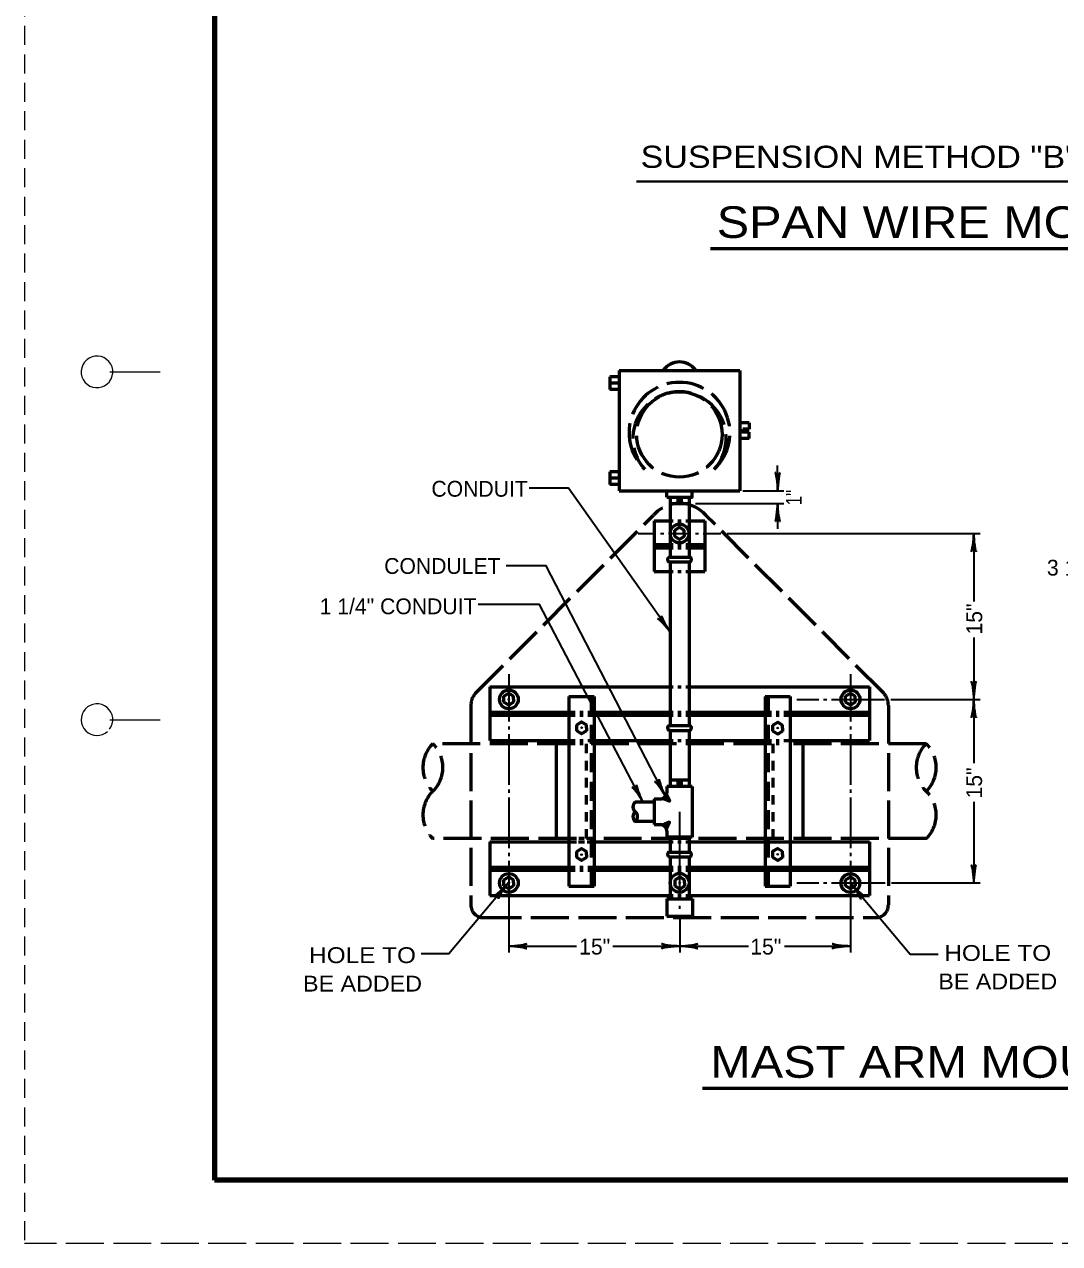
# Model space of a CAD drawing. Extents: x -1 to 679, y 1 to 441.
# Drawn here: x -1.2 to 162.4, y 0.8 to 193.5 of the extents above; entities that cross this region are included whole.
import ezdxf
from ezdxf.enums import TextEntityAlignment as Align

# ---------------------------------------------------------------- set-up
doc = ezdxf.new("R2010")
doc.units = 0
for name, pattern in [('LONG_DASHED', [7.5, 6, -1.5]), ('MEDIUM_DASHED', [4.5, 3, -1.5]), ('SHORT_DASHED', [2.7, 1.5, -1.2])]:
    doc.linetypes.add(name, pattern=pattern)
doc.layers.add('1', color=7, linetype='Continuous', lineweight=35)
doc.layers.add('61', color=7, linetype='Continuous', lineweight=35)

msp = doc.modelspace()

# ---------------------------------------------------------------- hatches: boundary and pattern name
at = {"layer": '1'}
for points in [[(75.433, 86.822, 1), (75.183, 86.822, 1)], [(129.442, 86.794, 1), (129.192, 86.794, 1)], [(86.96, 82.329, 1), (86.71, 82.329, 1)], [(117.958, 82.283, 1), (117.708, 82.283, 1)], [(86.956, 62.257, 1), (86.706, 62.257, 1)], [(117.958, 62.317, 1), (117.708, 62.317, 1)], [(75.456, 57.834, 1), (75.206, 57.834, 1)], [(102.471, 57.779, 1), (102.221, 57.779, 1)], [(129.454, 57.788, 1), (129.204, 57.788, 1)]]:
    msp.add_hatch(color=256, dxfattribs=at).paths.add_polyline_path(points)

# ---------------------------------------------------------------- linework, layer by layer
at = {"layer": '1', "linetype": 'MEDIUM_DASHED', "lineweight": 13}
msp.add_line((-1.178, 440.796), (-1.238, 0.756), dxfattribs=at)
at = {"layer": '1', "lineweight": 40}
msp.add_line((95.529, 168.697), (237.44, 168.697), dxfattribs=at)
at = {"layer": '1', "lineweight": 53}
for p, q in [((107.221, 158.112), (227.893, 158.112)), ((92.794, 138.806), (92.794, 119.806)), ((92.794, 138.806), (111.829, 138.806)), ((111.829, 138.806), (111.829, 119.806)), ((92.794, 137.806), (91.294, 137.806)), ((91.294, 137.806), (91.294, 135.806)), ((92.794, 136.806), (91.294, 136.806)), ((92.794, 135.806), (91.294, 135.806)), ((113.329, 130.556), (111.829, 130.556)), ((113.329, 129.556), (112.329, 129.556)), ((113.329, 130.556), (113.329, 129.556)), ((113.329, 128.056), (111.829, 128.056)), ((113.329, 128.056), (113.329, 129.056)), ((92.794, 122.806), (91.294, 122.806)), ((91.294, 122.806), (91.294, 120.806)), ((92.794, 121.806), (91.294, 121.806)), ((92.794, 120.806), (91.294, 120.806)), ((92.794, 119.806), (111.829, 119.806)), ((100.294, 118.791), (100.294, 119.791)), ((100.829, 118.791), (100.829, 109.291)), ((100.829, 117.791), (103.829, 117.791)), ((101.829, 118.291), (102.829, 118.291)), ((103.829, 118.791), (103.829, 115.041)), ((102.044, 115.041), (102.579, 115.041)), ((103.829, 115.029), (103.829, 109.291)), ((106.329, 115.041), (106.329, 107.041)), ((101.552, 112.585), (101.552, 113.552)), ((103.073, 113.068), (103.073, 113.552)), ((103.073, 113.068), (103.073, 112.585)), ((98.294, 110.791), (100.829, 110.791)), ((100.829, 110.791), (101.294, 110.791)), ((102.044, 111.291), (102.579, 111.291)), ((102.044, 110.791), (102.579, 110.791)), ((103.329, 111.291), (103.829, 111.291)), ((103.329, 110.791), (103.829, 110.791)), ((103.829, 111.291), (106.329, 111.291)), ((103.829, 110.791), (106.329, 110.791)), ((100.829, 109.291), (103.829, 109.291)), ((100.829, 108.541), (103.829, 108.541)), ((100.829, 108.541), (100.829, 84.291)), ((103.829, 108.541), (103.829, 82.666)), ((98.294, 107.041), (101.294, 107.041)), ((102.044, 107.041), (102.579, 107.041)), ((103.329, 107.041), (106.329, 107.041)), ((72.329, 88.791), (101.294, 88.791)), ((102.044, 88.791), (102.579, 88.791)), ((103.329, 88.791), (132.329, 88.791)), ((132.329, 88.791), (132.329, 80.291)), ((74.568, 86.347), (74.568, 87.314)), ((76.089, 86.831), (76.089, 87.314)), ((76.089, 86.831), (76.089, 86.347)), ((84.829, 87.291), (84.829, 57.291)), ((84.829, 87.291), (88.829, 87.291)), ((88.829, 87.291), (88.829, 57.291)), ((115.829, 87.291), (115.829, 57.291)), ((115.829, 87.291), (119.829, 87.291)), ((119.829, 87.291), (119.829, 57.291)), ((128.568, 86.347), (128.568, 87.314)), ((130.089, 86.831), (130.089, 87.314)), ((130.089, 86.831), (130.089, 86.347)), ((72.329, 84.791), (85.829, 84.791)), ((72.329, 84.291), (85.829, 84.291)), ((86.579, 84.791), (87.079, 84.791)), ((86.579, 84.291), (87.079, 84.291)), ((87.829, 84.791), (101.294, 84.791)), ((87.829, 84.291), (101.294, 84.291)), ((100.829, 84.291), (100.829, 82.666)), ((102.044, 84.791), (102.579, 84.791)), ((102.044, 84.291), (102.579, 84.291)), ((103.329, 84.791), (116.829, 84.791)), ((103.329, 84.291), (116.829, 84.291)), ((117.579, 84.791), (118.079, 84.791)), ((117.579, 84.291), (118.079, 84.291)), ((118.829, 84.791), (132.329, 84.791)), ((118.829, 84.291), (132.329, 84.291)), ((86.077, 81.83), (86.077, 82.797)), ((87.598, 82.313), (87.598, 82.797)), ((87.598, 82.313), (87.598, 81.83)), ((100.829, 82.666), (103.829, 82.666)), ((100.829, 81.916), (103.829, 81.916)), ((100.829, 81.916), (100.829, 80.291)), ((103.829, 81.916), (103.829, 73.041)), ((117.076, 81.783), (117.076, 82.751)), ((118.597, 82.267), (118.597, 82.751)), ((118.597, 82.267), (118.597, 81.783)), ((72.329, 80.291), (85.829, 80.291)), ((82.829, 79.791), (82.829, 64.791)), ((86.579, 80.291), (87.079, 80.291)), ((87.829, 80.291), (101.294, 80.291)), ((100.829, 80.291), (100.829, 73.041)), ((102.044, 80.291), (102.579, 80.291)), ((103.329, 80.291), (116.829, 80.291)), ((117.579, 80.291), (118.079, 80.291)), ((118.829, 80.291), (132.329, 80.291)), ((121.829, 79.791), (121.829, 64.791)), ((103.829, 74.041), (100.829, 74.041)), ((102.829, 73.541), (101.829, 73.541)), ((104.329, 73.041), (100.33, 73.041)), ((100.33, 73.041), (100.33, 72.041)), ((104.329, 73.041), (104.329, 65.041)), ((98.329, 70.564), (95.329, 70.564)), ((98.329, 71.064), (98.329, 67.019)), ((98.329, 71.064), (99.329, 71.064)), ((98.329, 67.519), (95.329, 67.519)), ((98.329, 67.019), (99.329, 67.019)), ((100.333, 66.041), (100.333, 65.041)), ((72.329, 64.291), (86.029, 64.291)), ((86.342, 64.291), (87.319, 64.291)), ((87.695, 64.291), (101.294, 64.291)), ((104.329, 65.041), (100.333, 65.041)), ((100.829, 65.041), (100.829, 64.291)), ((100.829, 64.291), (100.829, 62.666)), ((102.044, 64.291), (102.579, 64.291)), ((103.329, 64.291), (132.329, 64.291)), ((103.829, 65.041), (103.829, 64.291)), ((103.829, 64.291), (103.829, 62.666)), ((132.329, 64.291), (132.329, 55.791)), ((86.069, 61.783), (86.069, 62.75)), ((87.59, 62.267), (87.59, 62.75)), ((87.59, 62.267), (87.59, 61.783)), ((100.829, 62.666), (103.829, 62.666)), ((100.829, 61.916), (103.829, 61.916)), ((100.829, 61.916), (100.829, 60.291)), ((103.829, 61.916), (103.829, 60.291)), ((118.597, 62.301), (118.597, 62.785)), ((118.597, 62.301), (118.597, 61.817)), ((72.329, 60.291), (85.829, 60.291)), ((72.329, 59.791), (85.829, 59.791)), ((86.579, 60.291), (87.079, 60.291)), ((86.579, 59.791), (87.079, 59.791)), ((87.829, 60.291), (101.294, 60.291)), ((87.829, 59.791), (101.294, 59.791)), ((100.829, 60.291), (100.829, 55.291)), ((102.044, 60.291), (102.579, 60.291)), ((102.044, 59.791), (102.579, 59.791)), ((103.329, 60.291), (132.329, 60.291)), ((103.329, 59.791), (132.329, 59.791)), ((103.829, 60.291), (103.829, 55.291)), ((74.569, 57.327), (74.569, 58.294)), ((76.09, 57.81), (76.09, 58.294)), ((101.603, 57.296), (101.603, 58.263)), ((103.124, 57.779), (103.124, 58.263)), ((128.557, 57.303), (128.557, 58.271)), ((130.078, 57.787), (130.078, 58.271)), ((76.09, 57.81), (76.09, 57.327)), ((84.829, 57.291), (88.829, 57.291)), ((103.124, 57.779), (103.124, 57.296)), ((115.829, 57.291), (119.829, 57.291)), ((130.078, 57.787), (130.078, 57.303)), ((72.329, 55.791), (101.294, 55.791)), ((100.333, 55.291), (104.378, 55.291)), ((100.333, 55.291), (100.333, 52.541)), ((102.044, 55.791), (102.579, 55.791)), ((103.329, 55.791), (132.329, 55.791)), ((104.378, 55.291), (104.378, 52.541)), ((100.333, 52.541), (104.378, 52.541)), ((105.933, 25.316), (220.597, 25.316))]:
    msp.add_line(p, q, dxfattribs=at)
at = {"layer": '1'}
for p, q in [((117.829, 119.806), (117.829, 123.806)), ((112.329, 119.806), (118.829, 119.806)), ((104.829, 117.791), (118.829, 117.791)), ((117.829, 117.791), (117.829, 113.791)), ((95.794, 113.041), (98.561, 113.041)), ((99.311, 113.041), (99.811, 113.041)), ((100.561, 113.041), (104.079, 113.041)), ((104.829, 113.041), (105.329, 113.041)), ((106.079, 113.041), (108.829, 113.041)), ((109.829, 113.041), (149.829, 113.041)), ((148.829, 113.041), (148.829, 102.304)), ((75.329, 90.791), (75.329, 83.291)), ((129.329, 90.791), (129.329, 83.291)), ((120.858, 86.791), (124.329, 86.791)), ((125.079, 86.791), (125.579, 86.791)), ((126.329, 86.791), (134.704, 86.791)), ((135.704, 86.791), (149.829, 86.791)), ((75.329, 82.541), (75.329, 82.041)), ((75.329, 81.291), (75.329, 73.291)), ((129.329, 82.541), (129.329, 82.041)), ((129.329, 81.291), (129.329, 73.291)), ((75.329, 72.541), (75.329, 72.041)), ((129.329, 72.541), (129.329, 72.041)), ((75.329, 71.291), (75.329, 63.291)), ((129.329, 71.291), (129.329, 63.291)), ((148.829, 70.63), (148.829, 57.791)), ((102.356, 62.666), (102.356, 69.041)), ((75.329, 62.541), (75.329, 62.041)), ((102.356, 62.166), (102.356, 62.416)), ((102.356, 55.291), (102.356, 61.916)), ((129.329, 62.541), (129.329, 62.041)), ((75.329, 61.291), (75.329, 46.791)), ((129.329, 61.291), (129.329, 46.791)), ((120.858, 57.791), (124.329, 57.791)), ((125.079, 57.791), (125.579, 57.791)), ((126.329, 57.791), (134.829, 57.791)), ((135.829, 57.791), (149.829, 57.791)), ((102.356, 53.666), (102.356, 54.166)), ((102.356, 52.166), (102.356, 46.791)), ((75.329, 47.791), (86.055, 47.791)), ((118.907, 47.791), (129.329, 47.791))]:
    msp.add_line(p, q, dxfattribs=at)
at = {"layer": '1', "linetype": 'LONG_DASHED', "lineweight": 53}
for p, q in [((70.207, 87.943), (98.208, 115.944)), ((134.45, 87.943), (106.449, 115.944)), ((69.329, 85.822), (69.329, 54.297)), ((135.329, 85.822), (135.329, 54.297)), ((85.829, 79.791), (63.329, 79.791)), ((87.079, 79.791), (86.579, 79.791)), ((116.829, 79.791), (87.829, 79.791)), ((118.079, 79.791), (117.579, 79.791)), ((141.329, 79.791), (118.829, 79.791)), ((86.011, 64.791), (63.329, 64.791)), ((87.238, 64.791), (86.387, 64.791)), ((141.329, 64.791), (87.614, 64.791)), ((71.329, 52.297), (133.329, 52.297))]:
    msp.add_line(p, q, dxfattribs=at)
at = {"layer": '1', "linetype": 'MEDIUM_DASHED', "lineweight": 53}
for p, q in [((88.329, 87.291), (88.329, 57.291)), ((116.329, 87.291), (116.329, 57.291))]:
    msp.add_line(p, q, dxfattribs=at)
at = {"layer": '1', "linetype": 'SHORT_DASHED', "lineweight": 53}
for p, q in [((87.579, 79.791), (87.579, 64.791)), ((117.079, 79.791), (117.079, 64.791))]:
    msp.add_line(p, q, dxfattribs=at)
at = {"layer": '1', "lineweight": 53}
for points in [[(113.329, 129.056), (112.329, 129.056), (112.329, 129.556)], [(100.294, 118.791), (104.329, 118.791), (104.329, 119.791)], [(98.294, 115.041), (100.829, 115.041), (101.294, 115.041)], [(98.294, 115.041), (98.294, 110.791), (98.294, 107.041)], [(101.552, 113.552), (102.312, 114.023), (103.073, 113.552)], [(103.329, 115.041), (103.829, 115.041), (106.329, 115.041)], [(103.073, 112.585), (102.312, 112.115), (101.552, 112.585)], [(98.294, 111.291), (100.829, 111.291), (101.294, 111.291)], [(72.329, 88.791), (72.329, 84.791), (72.329, 80.291)], [(74.568, 87.314), (75.329, 87.785), (76.089, 87.314)], [(128.568, 87.314), (129.329, 87.785), (130.089, 87.314)], [(76.089, 86.347), (75.329, 85.878), (74.568, 86.347)], [(130.089, 86.347), (129.329, 85.878), (128.568, 86.347)], [(86.077, 82.797), (86.838, 83.268), (87.598, 82.797)], [(117.076, 82.751), (117.837, 83.222), (118.597, 82.751)], [(87.598, 81.83), (86.838, 81.36), (86.077, 81.83)], [(118.597, 81.783), (117.837, 81.314), (117.076, 81.783)], [(100.251, 71.738), (100.736, 70.692), (99.645, 71.139)], [(100.255, 66.344), (100.74, 67.39), (99.649, 66.943)], [(72.329, 64.291), (72.329, 60.291), (72.329, 59.791), (72.329, 55.791)], [(86.069, 62.75), (86.829, 63.221), (87.59, 62.75)], [(87.59, 61.783), (86.829, 61.314), (86.069, 61.783)], [(117.076, 61.817), (117.076, 62.785), (117.837, 63.256), (118.597, 62.785)], [(118.597, 61.817), (117.837, 61.348), (117.076, 61.817)], [(74.569, 58.294), (75.33, 58.765), (76.09, 58.294)], [(101.603, 58.263), (102.364, 58.734), (103.124, 58.263)], [(128.557, 58.271), (129.317, 58.742), (130.078, 58.271)], [(76.09, 57.327), (75.33, 56.857), (74.569, 57.327)], [(103.124, 57.296), (102.364, 56.826), (101.603, 57.296)], [(130.078, 57.303), (129.317, 56.834), (128.557, 57.303)]]:
    msp.add_lwpolyline(points, dxfattribs=at)
at = {"layer": '1'}
for points in [[(100.829, 97.467), (84.77, 120.225), (78.531, 120.225)], [(100.077, 71.452), (81.249, 107.916), (74.936, 107.916)], [(96.515, 70.564), (80.185, 101.815), (70.468, 101.815)], [(148.829, 96.591), (148.829, 86.791), (148.829, 76.705)], [(75.228, 57.751), (65.856, 46.593), (61.474, 46.593)], [(129.422, 57.669), (138.793, 46.511), (143.175, 46.511)], [(91.751, 47.791), (102.356, 47.791), (113.21, 47.791)]]:
    msp.add_lwpolyline(points, dxfattribs=at)
at = {"layer": '1', "linetype": 'LONG_DASHED', "lineweight": 53}
msp.add_circle((102.301, 128.701), 6.75, dxfattribs=at)
at = {"layer": '1', "lineweight": 53}
for centre in [(102.325, 113.043), (75.341, 86.805), (129.341, 86.805), (75.342, 57.785), (102.334, 57.802), (129.33, 57.761)]:
    msp.add_circle(centre, 1.483, dxfattribs=at)
at = {"layer": '1', "lineweight": 13}
for centre in [(75.308, 86.822), (129.317, 86.794), (86.835, 82.329), (117.833, 82.283), (86.831, 62.257), (117.833, 62.317), (75.331, 57.834), (102.346, 57.779), (129.329, 57.788)]:
    msp.add_circle(centre, 0.125, dxfattribs=at)
at = {"layer": '1', "lineweight": 53}
for centre, radius, start, end in [((102.311, 137), 3.159, 37.18292, 142.81708), ((100.797, 108.917), 0.376, 85.2092, 274.79081), ((103.86, 108.917), 0.376, 265.20919, 94.7908), ((100.797, 82.292), 0.376, 85.2092, 274.79081), ((103.86, 82.292), 0.376, 265.20919, 94.7908), ((99.233, 72.163), 1.103, 291.91656, 353.67636), ((99.233, 72.163), 1.103, 291.91738, 337.37313), ((95.903, 69.803), 0.954, 127.04437, 232.95563), ((99.233, 72.163), 1.103, 274.9623, 291.91656), ((95.903, 68.28), 0.954, 127.04437, 232.95563), ((94.743, 68.28), 0.954, 307.04437, 52.95563), ((99.237, 65.919), 1.103, 68.08344, 85.22882), ((99.237, 65.919), 1.103, 6.34541, 68.08344), ((99.237, 65.919), 1.103, 22.62687, 68.08262), ((100.797, 62.292), 0.376, 85.2092, 274.79081), ((103.86, 62.292), 0.376, 265.20919, 94.7908)]:
    msp.add_arc(centre, radius, start, end, dxfattribs=at)
at = {"layer": '1', "linetype": 'LONG_DASHED', "lineweight": 53}
for centre, radius, start, end in [((102.311, 128.964), 7.975, 313.60282, 226.39718), ((102.312, 128.087), 7.364, 318.31863, 221.68137), ((102.329, 112.274), 5.518, 41.68937, 138.31063), ((72.329, 85.822), 3, 135, 180), ((132.329, 85.822), 3, 0, 45), ((67.035, 76.041), 5.273, 134.66789, 225.33211), ((59.642, 76.041), 5.273, 314.66789, 45.33211), ((145.015, 76.041), 5.273, 134.66789, 225.33211), ((137.622, 76.041), 5.273, 314.66789, 45.33211), ((67.035, 68.541), 5.273, 134.66789, 225.33211), ((137.622, 68.541), 5.273, 314.66789, 45.33211), ((71.329, 54.297), 2, 180, 270), ((133.329, 54.297), 2, 270, 0)]:
    msp.add_arc(centre, radius, start, end, dxfattribs=at)
at = {"layer": '1', "lineweight": 40}
for centre, major_axis, ratio, start_param, end_param in [((117.552, 120.898), (0.156, -1.786), 0.122415, 0.8963533, 3.1415927), ((117.552, 120.898), (0.156, -1.786), 0.122415, 0.8963533, 3.1415927), ((118.04, 120.927), (-0.176, -1.756), 0.07063, 3.1407148, 5.41811), ((118.04, 120.927), (-0.176, -1.756), 0.07063, 3.1407148, 5.41811), ((117.617, 116.671), (0.176, 1.756), 0.07063, 3.1407148, 5.41811), ((118.105, 116.7), (-0.156, 1.786), 0.122415, 0.8963533, 3.1415927), ((148.617, 111.921), (0.176, 1.756), 0.07063, 3.1407148, 5.41811), ((148.617, 111.921), (0.176, 1.756), 0.07063, 3.1407148, 5.41811), ((149.105, 111.95), (-0.156, 1.786), 0.122415, 0.8963533, 3.1415927), ((149.105, 111.95), (-0.156, 1.786), 0.122415, 0.8963533, 3.1415927), ((99.974, 98.2), (1.157, -1.369), 0.122415, 0.8963533, 3.1415927), ((99.974, 98.2), (1.157, -1.369), 0.122415, 0.8963533, 3.1415927), ((100.356, 98.505), (-0.869, 1.536), 0.07063, 6.2823074, 8.5597026), ((100.356, 98.505), (-0.869, 1.536), 0.07063, 6.2823074, 8.5597026), ((148.552, 87.883), (0.156, -1.786), 0.122415, 0.8963533, 3.1415927), ((148.552, 87.883), (0.156, -1.786), 0.122415, 0.8963533, 3.1415927), ((149.04, 87.912), (-0.176, -1.756), 0.07063, 3.1407148, 5.41811), ((149.04, 87.912), (-0.176, -1.756), 0.07063, 3.1407148, 5.41811), ((148.617, 85.671), (0.176, 1.756), 0.07063, 3.1407148, 5.41811), ((148.617, 85.671), (0.176, 1.756), 0.07063, 3.1407148, 5.41811), ((149.105, 85.7), (-0.156, 1.786), 0.122415, 0.8963533, 3.1415927), ((149.105, 85.7), (-0.156, 1.786), 0.122415, 0.8963533, 3.1415927), ((96.184, 71.655), (0.658, -1.638), 0.07063, 3.1407148, 5.41811), ((99.33, 72.294), (0.958, -1.515), 0.122415, 0.8963533, 3.1415927), ((99.33, 72.294), (0.958, -1.515), 0.122415, 0.8963533, 3.1415927), ((99.751, 72.544), (0.65, -1.641), 0.07063, 3.1407148, 5.41811), ((99.751, 72.544), (0.65, -1.641), 0.07063, 3.1407148, 5.41811), ((95.765, 71.403), (0.965, -1.51), 0.122415, 0.8963533, 3.1415927), ((148.552, 58.883), (0.156, -1.786), 0.122415, 0.8963533, 3.1415927), ((149.04, 58.912), (-0.176, -1.756), 0.07063, 3.1407148, 5.41811), ((74.345, 57.029), (-1.264, -1.232), 0.07063, 6.2823074, 8.5597026), ((74.737, 56.738), (1.029, 1.468), 0.122415, 0.8963533, 3.1415927), ((129.912, 56.656), (-1.029, 1.468), 0.122415, 3.1415927, 5.386832), ((130.304, 56.947), (1.264, -1.232), 0.07063, 4.006668, 6.2840632), ((76.42, 48.068), (-1.786, -0.156), 0.122415, 0.8963533, 3.1415927), ((76.42, 48.068), (-1.786, -0.156), 0.122415, 0.8963533, 3.1415927), ((103.447, 48.068), (-1.786, -0.156), 0.122415, 0.8963533, 3.1415927), ((103.447, 48.068), (-1.786, -0.156), 0.122415, 0.8963533, 3.1415927), ((76.449, 47.58), (-1.756, 0.176), 0.07063, 3.1407148, 5.41811), ((76.449, 47.58), (-1.756, 0.176), 0.07063, 3.1407148, 5.41811), ((101.265, 47.515), (1.786, 0.156), 0.122415, 0.8963533, 3.1415927), ((101.265, 47.515), (1.786, 0.156), 0.122415, 0.8963533, 3.1415927), ((101.235, 48.003), (1.756, -0.176), 0.07063, 3.1407148, 5.41811), ((101.235, 48.003), (1.756, -0.176), 0.07063, 3.1407148, 5.41811), ((103.476, 47.58), (-1.756, 0.176), 0.07063, 3.1407148, 5.41811), ((103.476, 47.58), (-1.756, 0.176), 0.07063, 3.1407148, 5.41811), ((128.237, 47.515), (1.786, 0.156), 0.122415, 0.8963533, 3.1415927), ((128.208, 48.003), (1.756, -0.176), 0.07063, 3.1407148, 5.41811)]:
    msp.add_ellipse(centre, major_axis=major_axis, ratio=ratio, start_param=start_param, end_param=end_param, dxfattribs=at)
at = {"layer": '61', "lineweight": 13}
for p, q in [((12.242, 138.616), (20.242, 138.616)), ((12.262, 83.596), (20.242, 83.596))]:
    msp.add_line(p, q, dxfattribs=at)
at = {"layer": '61', "lineweight": 158}
msp.add_line((667.882, 10.756), (28.822, 10.776), dxfattribs=at)
at = {"layer": '61', "linetype": 'LONG_DASHED', "lineweight": 13}
msp.add_line((678.822, 0.776), (-1.238, 0.756), dxfattribs=at)
at = {"layer": '61', "lineweight": 158}
msp.add_lwpolyline([(667.862, 430.796), (28.822, 430.796), (28.822, 10.776)], dxfattribs=at)
at = {"layer": '61', "lineweight": 13}
for centre, start, end in [((10.24, 138.597), 322.67175, 321.71615), ((10.24, 83.597), 323.13009, 312.31439)]:
    msp.add_arc(centre, 2.5, start, end, dxfattribs=at)

# ---------------------------------------------------------------- texts
at = {"layer": '1', "width": 1.15}
for s, height, p in [('SUSPENSION METHOD "B" - DOUBLE HANGER UNITS', 3.5, (96.164, 170.857)), ('SPAN WIRE MOUNTING DETAILS', 5, (108.191, 159.776)), ('MAST ARM MOUNTING DETAIL', 5, (107.17, 26.979))]:
    msp.add_text(s, height=height, dxfattribs=at).set_placement(p)
at = {"layer": '1'}
for s, p in [('CONDUIT', (63.099, 118.86)), ('CONDULET', (55.632, 106.653)), ('1 1/4" CONDUIT', (45.433, 100.276)), ('15"', (86.455, 46.467)), ('15"', (113.501, 46.467))]:
    msp.add_text(s, height=2.5, dxfattribs=at).set_placement(p)
at = {"layer": '1', "width": 0.8}
msp.add_text('1"', height=2.5, rotation=90, dxfattribs=at).set_placement((121.632, 117.494))
at = {"layer": '1'}
msp.add_text('3 1/2" x 2 1/2" x 5/16" SIGN', height=2.5, dxfattribs=at).set_placement((180.945, 106.39), align=Align.CENTER)
for p in [(150.155, 97.067), (150.135, 71.142)]:
    msp.add_text('15"', height=2.5, rotation=90, dxfattribs=at).set_placement(p)
for s, width, p in [('HOLE TO', 1.15, (52.213, 45.115)), ('HOLE TO', 1.15, (152.619, 45.464)), ('BE ADDED', 1.1, (52.213, 40.615)), ('BE ADDED', 1.1, (152.619, 40.964))]:
    msp.add_text(s, height=2.5, dxfattribs=dict(at, width=width)).set_placement(p, align=Align.CENTER)

doc.saveas('drawing.dxf')
